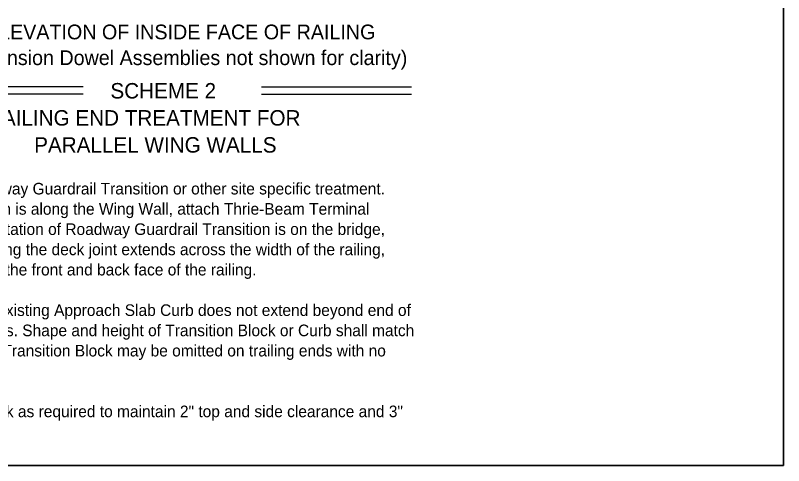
# Model space of a CAD drawing. Extents: x 0 to 41.1, y 0 to 26.
# Drawn here: x 27.71 to 41.07, y 0 to 7.83 of the extents above; entities that cross this region are included whole.
import ezdxf

# ---------------------------------------------------------------- set-up
doc = ezdxf.new("R2010")
doc.units = 0
doc.layers.add('Dimension', color=7, linetype='Continuous')
doc.layers.add('Miscellaneous1', color=7, linetype='Continuous')

msp = doc.modelspace()

# ---------------------------------------------------------------- linework, layer by layer
at = {"layer": 'Dimension'}
for p, q in [((28.887, 6.585), (26.28, 6.585)), ((31.988, 6.585), (34.595, 6.585)), ((28.887, 6.46), (26.28, 6.46)), ((31.988, 6.46), (34.595, 6.46))]:
    msp.add_line(p, q, dxfattribs=at)
msp.add_lwpolyline([(0, 0), (41.067, 0), (41.067, 25.97), (0, 25.97)], close=True, dxfattribs=at)
at = {"layer": 'Miscellaneous1'}
msp.add_lwpolyline([(0, 25.97), (41.067, 25.97), (41.067, 0), (0, 0)], close=True, dxfattribs=at)

# ---------------------------------------------------------------- texts
at = {"layer": 'Dimension'}
for s, height, p in [('PARTIAL ELEVATION OF INSIDE FACE OF RAILING', 0.256, (25.673, 7.411)), ('(Railing Reinforcing and Expansion Dowel Assemblies not shown for clarity)', 0.256, (23.03, 6.963)), ('SCHEME 2', 0.2688, (29.359, 6.382)), ('RAILING END TREATMENT FOR ', 0.2688, (27.212, 5.911)), ('PARALLEL WING WALLS', 0.2688, (28.033, 5.441)), ('1. See Roadway Plans for limiting station of Roadway Guardrail Transition or other site specific treatment.  ', 0.2016, (21.532, 4.714)), ('   If limiting station of Roadway Guardrail Transition is along the Wing Wall, attach Thrie-Beam Terminal ', 0.2016, (21.532, 4.362)), ('   Connector to railing as shown above. If limiting station of Roadway Guardrail Transition is on the bridge, ', 0.2016, (21.532, 4.01)), ('   see Sheet 1. On skewed bridges, if the skew along the deck joint extends across the width of the railing, ', 0.2016, (21.532, 3.658)), ('   the 2\'-6" minimum dimension shall apply to both the front and back face of the railing.', 0.2016, (21.532, 3.306)), ('2. Provide Transition Block (as shown) or Curb if existing Approach Slab Curb does not extend beyond end of ', 0.2016, (21.532, 2.602)), ('   existing End Bent Wing Wall, see Roadway Plans. Shape and height of Transition Block or Curb shall match ', 0.2016, (21.532, 2.25)), ('   existing bridge curb. Railing End Transition and Transition Block may be omitted on trailing ends with no ', 0.2016, (21.532, 1.898)), ('3. Field bend Dowel Bars 4L within Transition Block as required to maintain 2" top and side clearance and 3" ', 0.2016, (21.532, 0.842))]:
    msp.add_text(s, height=height, dxfattribs=at).set_placement(p)

doc.saveas('drawing.dxf')
